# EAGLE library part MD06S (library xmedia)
YAMAICHI CONNECTOR
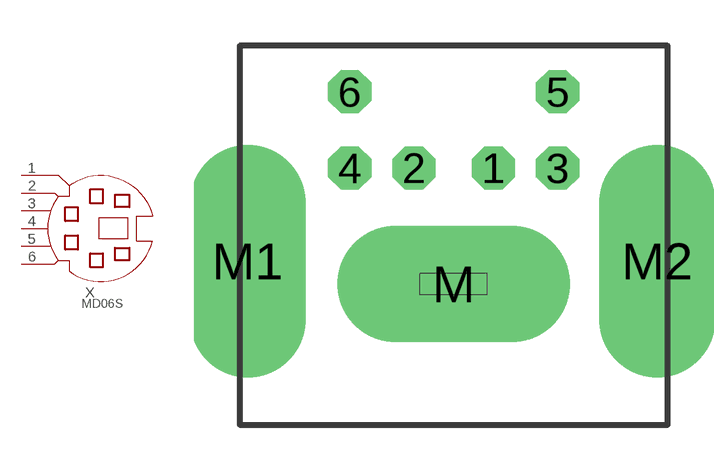
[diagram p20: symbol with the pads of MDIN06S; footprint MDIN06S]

Designator prefix X

## MD06S  [MDIN06S]
1  1  pas
2  2  pas
3  3  pas
4  4  pas
5  5  pas
6  6  pas

## Footprint MDIN06S (pad centres in mm)
Mini Din YAMAICHI CONNECTOR
drill 0.9 octagon: 1 1.3,8.5; 2 -1.3,8.5; 3 3.4,8.5; 4 -3.4,8.5; 5 3.4,11; 6 -3.4,11
drill 2.8 long: M 0,4.7
drill 2.8 pad 3 long: M1 -6.74,5.45; M2 6.66,5.45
